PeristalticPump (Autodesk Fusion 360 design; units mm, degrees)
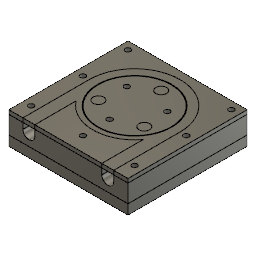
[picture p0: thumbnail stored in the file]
parameter "InDiameterBearing" = 8
parameter "OutDiameterBearing" = 22
parameter "BearingHolderDiameter" = 55
parameter "BearingHeight" = 7.5
parameter "BearingOffset" = 7
parameter "BaseThickness" = 6
parameter "BearingGap" = 1
parameter "TopThickness" = 3
parameter "TubeDiameter" = 9
parameter "TubeOffset" = 2
parameter "PumpTopDistance" = 40
parameter "PumpWidth" = 90
parameter "PumpBottomDistance" = 50
parameter "TubeLengthOutput" = 70
parameter "MotorDiameterHeight" = 3
parameter "MotorDiameter" = 22
parameter "ScrewDiameter" = 4
parameter "ScrewHeadDiameter" = 7
parameter "screwHeadHeight" = 4
parameter "ScrewHoleBearingOffset" = 7
parameter "ShaftDiameter" = 5
parameter "ShaftNotchDistance" = 4.55
parameter "ShaftLength" = 13.1 (= "12.6 mm + 0.5 mm")
parameter "GapBeetweenParts" = 1
parameter "DistanceScrewMotor" = 31
parameter "ScrewMotorDiameter" = 3
parameter "ScrewMotorHeadDiameter" = 7
parameter "ScrewMotorHeadHeight" = 2.5
sketch "Sketch1" plane through (0, 0, 0) normal (0, 1, 0) x axis (1, 0, 0)
  circle C1 centre (0, 0) radius 27.5
  point P1 (0, 0)
  point P2 (0, 0)
  coincident P1 P2
  dimension "d4" diameter C1 = 55 (= "BearingHolderDiameter")
extrude "Extrude1" new body sketch "Sketch1" along normal blind 7.5 (= "BearingHeight")
sketch "Sketch2" plane through (0, 7.5, 0) normal (0, 1, 0) x axis (-1, 0, 0)
  line L1 (0, -27.5) -> (0, 0)
  line L2 (23.8157, 13.75) -> (0, 0)
  line L3 (-23.8157, 13.75) -> (0, 0)
  circle C1 centre (0, 0) radius 27.5
  circle C2 centre (0, 0) radius 20
  circle C3 centre (0, -20) radius 11.5
  circle C4 centre (-17.3205, 10) radius 11.5
  circle C5 centre (17.3205, 10) radius 11.5
  point P3 (0, 0)
  point P4 (0, 0)
  point P5 (0, -27.5)
  point P10 (0, -20)
  point P11 (-17.3205, 10)
  point P12 (17.3205, 10)
  concentric C1 C2
  coincident P3 P4
  coincident C1 P5
  vertical L1
  coincident C2 P10
  coincident L1 P10
  coincident C2 P11
  coincident L3 P11
  coincident C2 P12
  coincident L2 P12
  dimension "d12" diameter C3 = 23 (= "OutDiameterBearing + BearingGap")
  dimension "d13" diameter C4 = 23 (= "OutDiameterBearing + BearingGap")
  dimension "d14" diameter C5 = 23 (= "OutDiameterBearing + BearingGap")
  dimension "d11" C-Pattern1-Angle = 360
extrude "Extrude2" cut sketch "Sketch2" profile of C1 C3 C4 C5 to an object
extrude "Extrude3" new body sketch "Sketch1" no distance stored
sketch "Sketch3" plane through (0, 0, 0) normal (0, 1, 0) x axis (1, 0, 0)
  circle C1 centre (17.3205, -10) radius 4
  circle C2 centre (-17.3205, -10) radius 4
  circle C3 centre (0, 20) radius 4
  point P2 (17.3205, -10)
  point P5 (17.3205, -10)
  point P3 (-17.3205, -10)
  point P6 (-17.3205, -10)
  point P4 (0, 20)
  point P7 (0, 20)
  coincident P2 P5
  coincident P3 P6
  coincident P4 P7
  dimension "d20" diameter C1 = 8 (= "InDiameterBearing")
  dimension "d21" diameter C2 = 8 (= "InDiameterBearing")
  dimension "d22" diameter C3 = 8 (= "InDiameterBearing")
extrude "Extrude4" new body sketch "Sketch3" along normal blind 10.5 (= "BearingHeight + TopThickness")
sketch "Sketch1" plane through (0, 7.5, 0) normal (0, 1, 0) x axis (-1, 0, 0)
  arc A1 centre (0, -20) radius 11.5 clockwise from (-10.0444, -25.6) to (10.0444, -25.6)
  arc A2 centre (0, 0) radius 27.5 clockwise from (27.1925, 4.1013) to (10.0444, -25.6)
  arc A3 centre (17.3205, 10) radius 11.5 clockwise from (27.1925, 4.1013) to (17.148, 21.4987)
  arc A4 centre (0, 0) radius 27.5 clockwise from (-17.148, 21.4987) to (17.148, 21.4987)
  arc A5 centre (-17.3205, 10) radius 11.5 clockwise from (-17.148, 21.4987) to (-27.1925, 4.1013)
  arc A6 centre (0, 0) radius 27.5 clockwise from (-10.0444, -25.6) to (-27.1925, 4.1013)
  circle C1 centre (0, 0) radius 27.5
  circle C2 centre (0, 0) radius 27.5
  concentric C1 C2
  dimension "d26" diameter C2 = 55 (= "BearingHolderDiameter")
extrude "Extrude1" new body sketch "Sketch1" along normal blind 3 (= "TopThickness")
sketch "Sketch2" plane through (0, 10.5, 0) normal (0, 1, 0) x axis (-1, 0, 0)
  circle C1 centre (0, 0) radius 27.5
  circle C2 centre (0, -20) radius 4
  circle C3 centre (-17.3205, 10) radius 4
  circle C4 centre (17.3205, 10) radius 4
  point P3 (0, -20)
  point P6 (0, -20)
  point P5 (-17.3205, 10)
  point P7 (-17.3205, 10)
  point P4 (17.3205, 10)
  point P8 (17.3205, 10)
  coincident P3 P6
  coincident P5 P7
  coincident P4 P8
  dimension "d30" diameter C2 = 8 (= "InDiameterBearing")
  dimension "d31" diameter C3 = 8 (= "InDiameterBearing")
  dimension "d32" diameter C4 = 8 (= "InDiameterBearing")
extrude "Extrude2" cut sketch "Sketch2" profile of C2 C3 C4 to an object
sketch "Sketch1" plane through (0, 0, 0) normal (0, 1, 0) x axis (1, 0, 0)
  line L1 (-45, -50) -> (-45, 40)
  line L2 (45, -50) -> (-45, -50)
  line L3 (45, 40) -> (45, -50)
  line L4 (-45, 40) -> (45, 40)
  circle C1 centre (0, 0) radius 28
  point P6 (0, 0)
  point P7 (0, 0)
  point P1 (0, 0)
  vertical L1
  perpendicular L1 L2
  perpendicular L2 L3
  perpendicular L3 L4
  coincident P6 P7
  dimension "d38" distance L4 P6 = 40 (= "PumpTopDistance")
  dimension "d42" distance L1 P6 = 45 (= "PumpWidth / 2")
  dimension "d43" distance P1 L3 = 45 (= "PumpWidth / 2")
  dimension "d44" distance P1 L2 = 50 (= "PumpBottomDistance")
  dimension "d45" diameter C1 = 56 (= "BearingHolderDiameter + GapBeetweenParts")
extrude "Extrude1" new body sketch "Sketch1" along normal blind 7.5 (= "BearingHeight") and against normal blind 6 (= "BaseThickness")
sketch "Sketch5" plane through (0, -6, 0) normal (0, -1, 0) x axis (1, 0, 0)
  line L1 (45, -40) -> (-45, -40)
  line L2 (45, 50) -> (45, -40)
  line L3 (-45, 50) -> (45, 50)
  line L4 (-45, -40) -> (-45, 50)
  circle C1 centre (0, 0) radius 28
work_plane "WorkPlane3" AlongDistance -4.5 (= "-( TubeDiameter / 2 )")
sketch "Sketch6" plane through (0, 3, 5) normal (0, 1, 0) x axis (1, 0, 0)
  line L1 (-29.75, -65) -> (-29.75, 5)
  line L2 (29.75, -65) -> (29.75, 5)
  arc A1 centre (0, 5) radius 29.75 clockwise from (-29.75, 5) to (29.75, 5)
  point P2 (0, 5)
  point P3 (0, 5)
  point P4 (-29.75, 5)
  point P5 (-29.75, -65)
  point P6 (29.75, 5)
  point P7 (29.75, -65)
  coincident P2 P3
  vertical L1
  tangent L1 A1
  tangent L2 A1
  parallel L1 L2
  dimension "d56" diameter A1 = 59.5 (= "BearingHolderDiameter + ( TubeDiameter / 2 )")
  dimension "d57" distance P4 P5 = 70 (= "TubeLengthOutput")
  dimension "d58" distance P6 P7 = 70 (= "TubeLengthOutput")
sketch "Sketch7" plane through (0, 0, 50) normal (0, 0, 1) x axis (1, 0, 0)
  line L1 (45, 7.5) -> (45, -6)
  line L2 (-45, 7.5) -> (45, 7.5)
  line L3 (-45, -6) -> (-45, 7.5)
  line L4 (45, -6) -> (-45, -6)
work_plane "WorkPlane4" sketch "Sketch7" AlongDistance 70
sketch "Sketch10" plane through (0, 1, 70) normal (0, 0, 1) x axis (1, 0, 0)
  line L1 (45, 6.5) -> (45, -7)
  line L2 (-45, 6.5) -> (45, 6.5)
  line L3 (-45, -7) -> (-45, 6.5)
  line L4 (45, -7) -> (-45, -7)
  line L5 (-34.25, 2) -> (-34.25, 6.5)
  line L6 (-25.25, 2) -> (-25.25, 6.5)
  line L7 (-25.25, 6.5) -> (-34.25, 6.5)
  circle C1 centre (-29.75, 2) radius 4.5
  point P2 (-29.75, 2)
  point P3 (-29.75, 2)
  point P8 (-34.25, 6.5)
  point P9 (-34.25, 2)
  point P10 (-25.25, 6.5)
  point P11 (-25.25, 2)
  coincident P2 P3
  coincident L2 P8
  coincident C1 P9
  tangent C1 L5
  coincident L2 P10
  coincident C1 P11
  tangent C1 L6
  parallel L3 L5
  parallel L3 L6
  dimension "d60" diameter C1 = 9 (= "TubeDiameter")
sweep "Sweep1" sketch "Sketch10" TwistAngle 0 TaperAngle 0
sketch "Sketch2" plane through (0, 7.5, 0) normal (0, 1, 0) x axis (-1, 0, 0)
  line L1 (-34.25, 50) -> (-34.25, 0)
  line L2 (-45, 50) -> (-34.25, 50)
  line L3 (-45, -40) -> (-45, 50)
  line L4 (45, -40) -> (-45, -40)
  line L5 (45, 50) -> (45, -40)
  line L6 (34.25, 50) -> (45, 50)
  line L7 (34.25, 0) -> (34.25, 50)
  line L8 (-25.25, 12.1011) -> (-25.25, 50)
  line L9 (25.25, 50) -> (25.25, 12.1011)
  line L10 (-25.25, 50) -> (25.25, 50)
  line L11 (-45, -40) -> (45, -40)
  line L12 (-45, 50) -> (-45, -40)
  line L13 (45, 50) -> (-45, 50)
  line L14 (45, -40) -> (45, 50)
  arc A1 centre (0, 0) radius 34.25 clockwise from (34.25, 0) to (-34.25, 0)
  arc A2 centre (0, 0) radius 28 clockwise from (-25.25, 12.1011) to (25.25, 12.1011)
  circle C1 centre (0, 0) radius 27.5
  point P6 (45, -40)
  point P16 (45, -40)
  point P5 (-45, -40)
  point P17 (-45, -40)
  point P18 (-45, -40)
  point P4 (-45, 50)
  point P19 (-45, 50)
  point P20 (-45, 50)
  point P7 (45, 50)
  point P21 (45, 50)
  point P22 (45, -40)
  point P1 (0, 0)
  point P23 (0, 0)
  coincident P6 P16
  coincident P5 P17
  coincident P5 P18
  coincident P4 P19
  coincident P4 P20
  coincident P7 P21
  coincident P6 P22
  coincident P1 P23
  dimension "d73" diameter C1 = 55 (= "BearingHolderDiameter")
sketch "Sketch1" plane through (0, 7.5, 0) normal (0, 1, 0) x axis (-1, 0, 0)
  line L1 (45, 50) -> (-45, 50)
  line L2 (45, -40) -> (45, 50)
  line L3 (-45, -40) -> (45, -40)
  line L4 (-45, 50) -> (-45, -40)
  circle C1 centre (0, 0) radius 28
  point P1 (0, 0)
  point P6 (0, 0)
  horizontal L1
  vertical L2
  horizontal L3
  vertical L4
  coincident P1 P6
  dimension "d74" diameter C1 = 56 (= "BearingHolderDiameter + GapBeetweenParts")
extrude "Extrude1" new body sketch "Sketch1" along normal blind 3 (= "TopThickness")
extrude "Extrude2" new body sketch "Sketch5" profile of C1 along normal blind 3 (= "MotorDiameterHeight")
sketch "Sketch12" plane through (0, -9, 0) normal (0, -1, 0) x axis (1, 0, 0)
  line L1 (45, -40) -> (-45, -40)
  line L2 (45, 50) -> (45, -40)
  line L3 (-45, 50) -> (45, 50)
  line L4 (-45, -40) -> (-45, 50)
  circle C1 centre (0, 0) radius 11
  point P1 (0, 0)
  point P6 (0, 0)
  coincident P1 P6
  dimension "d82" diameter C1 = 22 (= "MotorDiameter")
extrude "Extrude3" cut sketch "Sketch12" profile of C1 no distance stored
sketch "Sketch13" plane through (0, 7.5, 0) normal (0, 1, 0) x axis (-1, 0, 0)
  line L1 (-25.25, 12.1011) -> (-25.25, 50)
  line L2 (25.25, 50) -> (25.25, 12.1011)
  line L3 (-25.25, 50) -> (25.25, 50)
  arc A1 centre (0, 0) radius 28 clockwise from (-25.25, 12.1011) to (25.25, 12.1011)
  circle C1 centre (0, 0) radius 31.5
  point P1 (0, 0)
  point P7 (0, 0)
  coincident P1 P7
  dimension "d85" diameter C1 = 63 (= "BearingHolderDiameter + BearingOffset + GapBeetweenParts")
extrude "Extrude4" cut sketch "Sketch13" profile of L1 A1 L2 C1 no distance stored
sketch "Sketch2" plane through (0, 10.5, 0) normal (0, 1, 0) x axis (-1, 0, 0)
  line L1 (45, -40) -> (-45, -40)
  line L2 (45, 50) -> (45, -40)
  line L3 (-45, 50) -> (45, 50)
  line L4 (-45, -40) -> (-45, 50)
  line L5 (45, 28) -> (-45, 28)
  line L6 (-45, 39) -> (45, 39)
  line L7 (0, 50) -> (0, 28)
  line L8 (39, 50) -> (39, -40)
  line L9 (0, 0) -> (0, 39)
  line L10 (45, 19.5) -> (0, 19.5)
  line L11 (0, -28) -> (0, -40)
  line L12 (45, -34) -> (-45, -34)
  line L13 (7.5, 39) -> (7.5, -34)
  line L14 (45, 2.5) -> (7.5, 2.5)
  circle C1 centre (0, 0) radius 28
  circle C2 centre (0, 39) radius 2
  circle C3 centre (39, 39) radius 2
  circle C4 centre (-39, 39) radius 2
  circle C5 centre (39, 0) radius 2
  circle C6 centre (-39, 0) radius 2
  circle C7 centre (39, -34) radius 2
  circle C8 centre (-39, -34) radius 2
  point P7 (-45, 28)
  point P8 (45, 28)
  point P9 (45, 39)
  point P10 (-45, 39)
  point P11 (0, 28)
  point P12 (0, 50)
  point P13 (0, 39)
  point P14 (39, -40)
  point P15 (39, 50)
  point P16 (39, 39)
  point P18 (0, 39)
  point P2 (0, 0)
  point P19 (0, 0)
  point P20 (0, 19.5)
  point P21 (45, 19.5)
  point P24 (0, -40)
  point P25 (0, -28)
  point P26 (-45, -34)
  point P27 (45, -34)
  point P28 (7.5, -34)
  point P29 (7.5, 39)
  point P30 (7.5, 2.5)
  point P31 (45, 2.5)
  coincident L4 P7
  coincident L2 P8
  perpendicular L2 L5
  tangent C1 L5
  coincident L2 P9
  coincident L4 P10
  perpendicular L4 L6
  coincident C1 P11
  midpoint L3 P12
  perpendicular L3 L7
  midpoint L6 L7
  midpoint L6 P13
  coincident L1 P14
  coincident L3 P15
  perpendicular L3 L8
  coincident L8 P16
  coincident L6 P16
  symmetric L7 C3 C4
  coincident P13 P18
  coincident P2 P19
  coincident L9 P20
  coincident L2 P21
  perpendicular L2 L10
  midpoint L9 P20
  symmetric C3 L10 C5
  symmetric C4 L10 C6
  midpoint L1 P24
  coincident C1 P25
  perpendicular L1 L11
  coincident L4 P26
  coincident L2 P27
  perpendicular L2 L12
  midpoint L11 L12
  coincident L12 P28
  coincident L6 P29
  perpendicular L6 L13
  midpoint L13 P30
  coincident L2 P31
  perpendicular L2 L14
  symmetric C3 L14 C7
  symmetric C4 L14 C8
  dimension "d90" diameter C2 = 4 (= "ScrewDiameter")
  dimension "d95" distance L2 L8 = 6
  dimension "d96" diameter C3 = 4 (= "ScrewDiameter")
extrude "Extrude5" cut sketch "Sketch2" profile of C2 C3 C4 C5 C6 C7 C8 to an object Side2Offset 0
sketch "Sketch14" plane through (0, -9, 0) normal (0, -1, 0) x axis (1, 0, 0)
  line L1 (45, -40) -> (-45, -40)
  line L2 (45, 50) -> (45, -40)
  line L3 (-45, 50) -> (45, 50)
  line L4 (-45, -40) -> (-45, 50)
  line L5 (-45, -40) -> (45, -40)
  line L6 (-45, 50) -> (-45, -40)
  line L7 (45, 50) -> (-45, 50)
  line L8 (45, -40) -> (45, 50)
  circle C1 centre (0, 0) radius 11
  circle C2 centre (-39, 39) radius 2
  circle C3 centre (-39, 0) radius 2
  circle C4 centre (-39, -34) radius 2
  circle C5 centre (39, -34) radius 2
  circle C6 centre (39, 0) radius 2
  circle C7 centre (39, 39) radius 2
  circle C8 centre (0, 39) radius 2
  circle C9 centre (-39, -33.75) radius 3.5
  circle C10 centre (-39, 0) radius 3.5
  circle C11 centre (-39, 39) radius 3.5
  circle C12 centre (0, 39) radius 3.5
  circle C13 centre (39, 39) radius 3.5
  circle C14 centre (39, 0) radius 3.5
  circle C15 centre (39, -34) radius 3.5
  circle C16 centre (-39, 0) radius 2
  circle C17 centre (0, 39) radius 2
  circle C18 centre (39, 0) radius 2
  circle C19 centre (39, -34) radius 2
  circle C20 centre (-39, 39) radius 2
  circle C21 centre (39, 39) radius 2
  circle C22 centre (-39, -34) radius 2
  circle C23 centre (39, -34) radius 2
  circle C24 centre (0, 0) radius 28
  concentric C2 C11
  concentric C8 C12
  concentric C7 C13
  concentric C6 C14
  concentric C5 C15
  dimension "d97" diameter C9 = 7 (= "ScrewHeadDiameter")
  dimension "d98" diameter C10 = 7 (= "ScrewHeadDiameter")
  dimension "d99" diameter C11 = 7 (= "ScrewHeadDiameter")
  dimension "d100" diameter C12 = 7 (= "ScrewHeadDiameter")
  dimension "d101" diameter C13 = 7 (= "ScrewHeadDiameter")
  dimension "d102" diameter C14 = 7 (= "ScrewHeadDiameter")
  dimension "d103" diameter C15 = 7 (= "ScrewHeadDiameter")
extrude "Extrude3" cut sketch "Sketch2" profile of C2 C3 C4 C5 C6 C7 C8 to an object
sketch "Sketch3" plane through (0, 10.5, 0) normal (0, 1, 0) x axis (-1, 0, 0)
extrude "Extrude6" cut sketch "Sketch14" profile of C2 C3 C4 C5 C6 C7 C8 C9 C10 C11 C12 C13 C14 C15 no distance stored
sketch "Sketch5" plane through (0, 0, 0) normal (0, 0, 1) x axis (1, 0, 0)
  curve K1 (-26.3959, 0) -> (-25.25, 3)
  line L1 (-25.25, 3) -> (-25.25, 7.5)
  curve K2 (-27.5, -0.8971) -> (-26.3959, 0)
  line L2 (-27.5, 7.4622) -> (-27.5, -0.8971)
  line L3 (-25.25, 7.5) -> (-27.5, 7.4622)
  point P6 (-27.5, -0.8971)
  point P7 (-27.5, -0.8971)
  point P4 (-25.25, 7.5)
  point P9 (-25.25, 7.5)
  coincident P6 P7
  vertical L2
  coincident P4 P9
revolve "Revolve1" sketch "Sketch5" AlongAngle 360
sketch "Sketch15" plane through (0, 10.5, 0) normal (0, 1, 0) x axis (-1, 0, 0)
  line L1 (45, -40) -> (-45, -40)
  line L2 (45, 50) -> (45, -40)
  line L3 (-45, 50) -> (45, 50)
  line L4 (-45, -40) -> (-45, 50)
  circle C1 centre (0, 0) radius 28
  circle C2 centre (-39, 0) radius 2
  circle C3 centre (39, -34) radius 2
  circle C4 centre (0, 39) radius 2
  circle C5 centre (-39, 39) radius 2
  circle C6 centre (39, 0) radius 2
  circle C7 centre (39, 39) radius 2
  circle C8 centre (-39, -34) radius 2
sketch "Sketch6" plane through (0, 7.5, 0) normal (0, 1, 0) x axis (-1, 0, 0)
  line L1 (21.4502, -13.321) -> (0, 0)
  arc A1 centre (0, 0) radius 25.25 clockwise from (-11.1946, -22.6328) to (-25.25, 0)
  arc A2 centre (0, -20) radius 11.5 clockwise from (-11.1946, -22.6328) to (11.1946, -22.6328)
  arc A3 centre (0, 0) radius 25.25 clockwise from (25.25, 0) to (11.1946, -22.6328)
  arc A4 centre (17.3205, 10) radius 11.5 clockwise from (25.1979, 1.6216) to (14.0033, 21.0112)
  arc A5 centre (-17.3205, 10) radius 11.5 clockwise from (-14.0033, 21.0112) to (-25.1979, 1.6216)
  circle C1 centre (0, 0) radius 25.25
  circle C2 centre (0, 0) radius 18.25
  circle C3 centre (15.5036, -9.6281) radius 2
  circle C4 centre (0.5863, 18.2406) radius 2
  circle C5 centre (-16.09, -8.6125) radius 2
  arc A6 centre (0, 0) radius 25.25 clockwise from (-14.0033, 21.0112) to (14.0033, 21.0112)
  arc A7 centre (0, 0) radius 25.25 clockwise from (-25.25, 0) to (-25.1979, 1.6216)
  arc A8 centre (0, 0) radius 25.25 clockwise from (25.1979, 1.6216) to (25.25, 0)
  point P4 (0, 0)
  point P13 (0, 0)
  point P14 (21.4502, -13.321)
  point P16 (15.5036, -9.6281)
  concentric A1 C1
  coincident P4 P13
  midpoint A3 P14
  coincident C2 P16
  coincident L1 P16
  dimension "d112" diameter C3 = 4 (= "ScrewDiameter")
  dimension "d114" C-Pattern1-Angle = 360
extrude "Extrude5" cut sketch "Sketch6" profile of C3 C4 C5 to an object Side2Offset 0
sketch "Sketch7" plane through (0, -6, 0) normal (0, -1, 0) x axis (1, 0, 0)
  circle C1 centre (-0.5863, 18.2406) radius 2
  circle C2 centre (-15.5036, -9.6281) radius 2
  circle C3 centre (16.09, -8.6125) radius 2
  circle C4 centre (-0.5863, 18.2406) radius 2
  circle C5 centre (-15.5036, -9.6281) radius 2
  circle C6 centre (16.09, -8.6125) radius 2
  circle C7 centre (-0.5863, 18.2406) radius 3.5
  circle C8 centre (16.09, -8.6125) radius 3.5
  circle C9 centre (-15.5036, -9.6281) radius 3.5
  circle C10 centre (0, 0) radius 27.5
  concentric C4 C7
  concentric C3 C8
  concentric C2 C9
  dimension "d123" diameter C7 = 7 (= "ScrewHeadDiameter")
  dimension "d124" diameter C8 = 7 (= "ScrewHeadDiameter")
  dimension "d125" diameter C9 = 7 (= "ScrewHeadDiameter")
extrude "Extrude6" cut sketch "Sketch7" profile of C1 C2 C3 C4 C5 C6 C7 C8 C9 no distance stored
sketch "Sketch8" plane through (0, 7.5, 0) normal (0, 1, 0) x axis (-1, 0, 0)
sketch "Sketch10" plane through (0, -6, 0) normal (0, -1, 0) x axis (1, 0, 0)
  line L1 (7, 0) -> (-4.7156, 0.0813)
  line L2 (7.0247, -2.5488) -> (-3.0249, -2.4791)
  line L3 (1.4451, 2.04) -> (-1.4166, 2.0599)
  circle C1 centre (0, 0) radius 2.5
  point P1 (0, 0)
  point P2 (0, 0)
  point P7 (-1.4166, 2.0599)
  point P8 (1.4451, 2.04)
  coincident P1 P2
  parallel L1 L2
  tangent C1 L2
  parallel L2 L3
  coincident C1 P7
  coincident C1 P8
  dimension "d133" diameter C1 = 5 (= "ShaftDiameter")
  dimension "d134" distance L2 L3 = 4.55 (= "ShaftNotchDistance")
extrude "Extrude7" cut sketch "Sketch10" profile of C1 L3 no distance stored
sketch "Sketch16" plane through (0, -6, 0) normal (0, 1, 0) x axis (-1, 0, 0)
  line L1 (45, -40) -> (-45, -40)
  line L2 (45, 50) -> (45, -40)
  line L3 (-45, 50) -> (45, 50)
  line L4 (-45, -40) -> (-45, 50)
  line L5 (-15.5, -15.5) -> (15.5, -15.5)
  line L6 (-15.5, 15.5) -> (-15.5, -15.5)
  line L7 (15.5, 15.5) -> (-15.5, 15.5)
  line L8 (15.5, -15.5) -> (15.5, 15.5)
  line L9 (-15.5, 15.5) -> (15.5, -15.5)
  line L10 (15.5, 15.5) -> (-15.5, -15.5)
  circle C1 centre (-39, 0) radius 3.5
  circle C2 centre (39, 39) radius 3.5
  circle C3 centre (-39, -34) radius 3.5
  circle C4 centre (-39, 39) radius 3.5
  circle C5 centre (39, 0) radius 3.5
  circle C6 centre (39, -33.75) radius 3.5
  circle C7 centre (0, 39) radius 3.5
  circle C8 centre (0, 0) radius 11
  circle C9 centre (15.5, -15.5) radius 1.5
  circle C10 centre (15.5, 15.5) radius 1.5
  circle C11 centre (-15.5, -15.5) radius 1.5
  circle C12 centre (-15.5, 15.5) radius 1.5
  circle C13 centre (15.5, -15.5) radius 3.5
  circle C14 centre (-15.5, -15.5) radius 3.5
  circle C15 centre (-15.5, 15.5) radius 3.5
  circle C16 centre (15.5, 15.5) radius 3.5
  point P18 (0, 0)
  point P9 (0, 0)
  point P14 (15.5, -15.5)
  point P19 (15.5, -15.5)
  point P17 (15.5, 15.5)
  point P20 (15.5, 15.5)
  point P15 (-15.5, -15.5)
  point P21 (-15.5, -15.5)
  point P16 (-15.5, 15.5)
  point P22 (-15.5, 15.5)
  point P23 (15.5, -15.5)
  point P24 (-15.5, -15.5)
  point P25 (-15.5, 15.5)
  point P26 (15.5, 15.5)
  perpendicular L5 L6
  parallel L5 L7
  parallel L6 L8
  horizontal L5
  coincident L9 P18
  coincident L10 P18
  coincident P9 P18
  coincident P14 P19
  coincident P17 P20
  coincident P15 P21
  coincident P16 P22
  coincident P14 P23
  coincident P15 P24
  coincident P16 P25
  coincident P17 P26
  dimension "d139" distance P16 P17 = 31 (= "DistanceScrewMotor")
  dimension "d140" distance L5 L7 = 31 (= "DistanceScrewMotor")
  dimension "d142" diameter C9 = 3 (= "ScrewMotorDiameter")
  dimension "d143" diameter C10 = 3 (= "ScrewMotorDiameter")
  dimension "d144" diameter C11 = 3 (= "ScrewMotorDiameter")
  dimension "d145" diameter C12 = 3 (= "ScrewMotorDiameter")
  dimension "d150" diameter C13 = 7 (= "ScrewMotorHeadDiameter")
  dimension "d151" diameter C14 = 7 (= "ScrewMotorHeadDiameter")
  dimension "d152" diameter C15 = 7 (= "ScrewMotorHeadDiameter")
  dimension "d153" diameter C16 = 7 (= "ScrewMotorHeadDiameter")
extrude "Extrude7" cut sketch "Sketch16" profile of C9 C10 C11 C12 to an object
extrude "Extrude8" cut sketch "Sketch16" profile of C9 C10 C11 C12 C13 C14 C15 C16 no distance stored
extrude "Extrude9" add of existing geometry blind 4.5
extrude "Extrude8" cut of existing geometry blind -0.5
extrude "Extrude9" cut of existing geometry blind -0.5
extrude "Extrude10" add of existing geometry blind 4
extrude "Extrude11" add of existing geometry blind 4
extrude "Extrude12" cut of existing geometry to an object
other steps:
extrude "Extrude3" cut sketch "Sketch6" profile of C3 C4 C5 to an object Side2Offset 0
sweep "Sweep1" sketch "Sketch10" TwistAngle 0 TaperAngle 0
create_component "CreateComponent1"
create_component "CreateComponent2"
create_component "CreateComponent3"
create_component "CreateComponent4"
extrude "Extrude2" cut sketch "Sketch2" profile of C2 C3 C4 C5 C6 C7 C8 to an object Side2Offset 0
